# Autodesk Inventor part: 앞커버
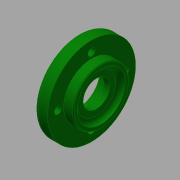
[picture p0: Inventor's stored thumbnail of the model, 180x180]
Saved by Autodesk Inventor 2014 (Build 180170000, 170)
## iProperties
Created: 2015-12
Part Number: 앞커버
Material: 일반
Document SubType Name: Modeling
Designer: mduedu
Density: 1 g/cm^3
Appearance: 진녹색
Author: mduedu
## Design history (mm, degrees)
sketch "스케치1"
  geometry: L1 (0, 0)-(14, 0); L2 (14, 0)-(14, 17.5); L3 (14, 17.5)-(8, 17.5); L4 (8, 17.5)-(8, 27.5); L5 (8, 27.5)-(0, 27.5); L6 (0, 27.5)-(0, 0)
  constraints: 12 end point, 4 parallel, 1 horizontal, 1 perpendicular
  dimensions: "d0" = 14 distance between parallel lines of L2 L6; "d2" = 8 distance of L4.end L5.end; "d3" = 55 diameter of L5 L1; "d4" = 35 diameter of L3 L1
revolve "회전1" sketch "스케치1" stored, may be unused: angle "d5" = 90 deg
hole "구멍1" diameter "d8" = 30; stored, may be unused: countersink angle "d12" = 90 deg, drill point angle "d14" = 0 deg; dims "d6" = 10, "d7" = 10, "d9" = 6, "d10" = 4, "d11" = 2, "d13" = 3
hole "구멍2" diameter "d17" = 25; stored, may be unused: countersink angle "d21" = 90 deg, drill point angle "d23" = 0 deg; dims "d15" = 10, "d16" = 10, "d18" = 6, "d19" = 4, "d20" = 2, "d22" = 7.3
hole "구멍3" diameter "d26" = 16.5; stored, may be unused: countersink angle "d30" = 90 deg, drill point angle "d32" = 0 deg; dims "d24" = 10, "d25" = 10, "d27" = 6, "d28" = 4, "d29" = 2, "d31" = 7.3
fillet "모깎기1" dims "d33" = 0.3
chamfer "모따기1" distance "d34" = 1; stored, may be unused: second distance "d35" = 2, angle "d36" = 30 deg
fillet "모깎기2" dims "d37" = 3
fillet "모깎기3" dims "d38" = 2
chamfer "모따기2" distance "d39" = 0.5; stored, may be unused: second distance "d40" = 2, angle "d41" = 45 deg
sketch "스케치2" dims "d42" = 42
  geometry: 9 further points
  constraints: 3 coincident, 2 vertical alignment, 9 other
  dimensions: "d46" = 360 deg dimension on point (0, 0) point (0, 21) (derived)
sketch "스케치3"
  geometry: 4 further points
hole "구멍4" sketch "스케치3" at (-21, 0), (0, -21), (21, 0), (0, 21) diameter "d50" = 4.5; stored, may be unused: countersink angle "d54" = 90 deg, drill point angle "d56" = 0 deg; dims "d51" = 6, "d52" = 8, "d53" = 4.6, "d55" = 8
node "솔리드1"
